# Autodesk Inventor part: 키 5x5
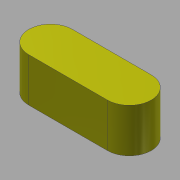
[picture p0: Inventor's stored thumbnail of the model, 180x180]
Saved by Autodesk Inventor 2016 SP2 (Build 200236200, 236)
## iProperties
Created: 2016-04
Part Number: 키 5x5
Document SubType Name: Modeling
Designer: mdu
Density: 7.86 g/cm^3
Mass: 2.54015 g
Surface Area: 2.9781 cm^2
Volume: 0.323175 cm^3
Material: 강철, 연강
Appearance: 강철 - 광택
Author: mdu
Revision Number: 1
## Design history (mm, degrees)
sketch "스케치1"
  geometry: L1 (-4.5, -2.5)-(4.5, -2.5); L2 (4.5, 2.5)-(-4.5, 2.5); A1 r 2.5 centre (4.5, 0) between (4.5, -2.5) and (4.5, 2.5); A2 r 2.5 centre (-4.5, 0) between (-4.5, 2.5) and (-4.5, -2.5); 2 further points
  constraints: 4 end point, 4 point on circle, 4 tangent, 2 centre point, 1 horizontal, 1 horizontal alignment, 1 midpoint, 1 parallel, 1 vertical alignment
  dimensions: "d0" = 5 distance between parallel lines of L1 L2; "d1" = 14 dimension on A1 A2
extrude "돌출1" new body sketch "스케치1" stored distance "d2" = 5; taper "d3" = 0 deg
node "솔리드1"
